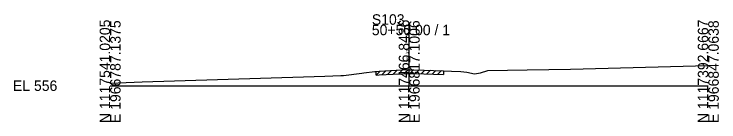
# Model space of a CAD drawing. Extents: x -26 to 163, y -10 to 45020.
# Drawn here: x -25.7 to 162.8, y 10490.3 to 10519.2 of the extents above; entities that cross this region are included whole.
import ezdxf

# ---------------------------------------------------------------- set-up
doc = ezdxf.new("R2010")
doc.units = 0
for name, color, linetype in [('RD_GPK_XS_Cell', 7, 'Continuous'), ('RD_XS_ExGround', 7, 'Continuous'), ('RD_XS_ExPaveRet', 7, 'Continuous'), ('RD_XS_TX_Elev_EX', 7, 'Continuous')]:
    doc.layers.add(name, color=color, linetype=linetype)

msp = doc.modelspace()

# ---------------------------------------------------------------- linework, layer by layer
at = {"layer": 'RD_GPK_XS_Cell'}
for p, q in [((80, 10500), (80, 10516.31)), ((0, 10500), (80, 10500)), ((80, 10500), (160, 10500))]:
    msp.add_line(p, q, dxfattribs=at)
at = {"layer": 'RD_XS_ExGround'}
for p, q in [((123.13, 10504.38), (160, 10505.44)), ((62.44, 10502.71), (67.33, 10503.39)), ((67.33, 10503.39), (67.9, 10503.46)), ((67.9, 10503.46), (70.83, 10503.78)), ((70.83, 10503.78), (71.18, 10503.82)), ((71.18, 10503.82), (71.97, 10503.86)), ((71.97, 10503.86), (79.53, 10504.29)), ((79.53, 10504.29), (80, 10504.27)), ((80, 10504.27), (81.26, 10504.24)), ((81.26, 10504.24), (89.16, 10504.01)), ((89.16, 10504.01), (91.35, 10503.91)), ((91.35, 10503.91), (93.78, 10503.81)), ((93.78, 10503.81), (95.38, 10503.58)), ((95.38, 10503.58), (97.5, 10503.15)), ((97.5, 10503.15), (99.06, 10503.47)), ((99.06, 10503.47), (101.01, 10504.05)), ((101.01, 10504.05), (111.52, 10504.21)), ((111.52, 10504.21), (123.13, 10504.38)), ((8.57, 10501.02), (51.7, 10502.41)), ((51.7, 10502.41), (57.4, 10502.53)), ((57.4, 10502.53), (61.75, 10502.68)), ((61.75, 10502.68), (62.44, 10502.71)), ((0, 10500.65), (8.57, 10501.02))]:
    msp.add_line(p, q, dxfattribs=at)
at = {"layer": 'RD_XS_ExPaveRet'}
for p, q in [((71.18, 10502.82), (72.24, 10503.87)), ((71.18, 10502.82), (71.18, 10503.82)), ((71.97, 10502.86), (79.53, 10503.29)), ((72.68, 10502.9), (73.74, 10503.96)), ((74.18, 10502.98), (75.24, 10504.04)), ((75.68, 10503.07), (76.74, 10504.13)), ((77.18, 10503.15), (78.24, 10504.21)), ((78.68, 10503.24), (79.73, 10504.28)), ((79.53, 10503.29), (80, 10503.27)), ((80, 10503.27), (81.26, 10503.24)), ((80.18, 10503.27), (81.16, 10504.24)), ((81.26, 10503.24), (89.16, 10503.01)), ((81.68, 10503.22), (82.66, 10504.2)), ((83.18, 10503.18), (84.16, 10504.15)), ((84.68, 10503.14), (85.66, 10504.11)), ((86.18, 10503.1), (87.16, 10504.07)), ((87.68, 10503.05), (88.66, 10504.03)), ((89.18, 10504.01), (89.18, 10503.01)), ((71.18, 10502.82), (71.97, 10502.86)), ((89.16, 10503.01), (89.18, 10503.01))]:
    msp.add_line(p, q, dxfattribs=at)

# ---------------------------------------------------------------- texts
at = {"layer": 'RD_GPK_XS_Cell'}
for s, p in [('S103', (70, 10516.31)), ('50+50.00 / 1', (70, 10513.51)), ('EL 556', (-26, 10498.6))]:
    msp.add_text(s, height=2.8, dxfattribs=at).set_placement(p)
for s, p in [('N 1117541.0205', (0, 10490)), ('E 1966787.1375', (2.8, 10490)), ('N 1117466.8436', (80, 10490)), ('E 1966817.1006', (82.8, 10490)), ('N 1117392.6667', (160, 10490)), ('E 1966847.0638', (162.8, 10490))]:
    msp.add_text(s, height=2.8, rotation=90, dxfattribs=at).set_placement(p)
at = {"layer": 'RD_XS_TX_Elev_EX'}
msp.add_text('560.27', height=0.8, rotation=90, dxfattribs=at).set_placement((79.9, 10506.27))

doc.saveas('drawing.dxf')
